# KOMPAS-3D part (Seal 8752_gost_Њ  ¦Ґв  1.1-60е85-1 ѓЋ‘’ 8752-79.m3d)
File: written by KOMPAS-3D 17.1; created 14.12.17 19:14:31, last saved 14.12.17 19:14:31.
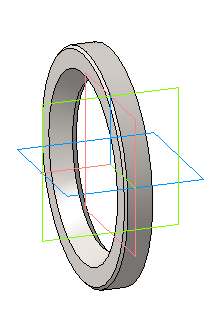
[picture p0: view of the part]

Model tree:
1. Операция без истории:1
